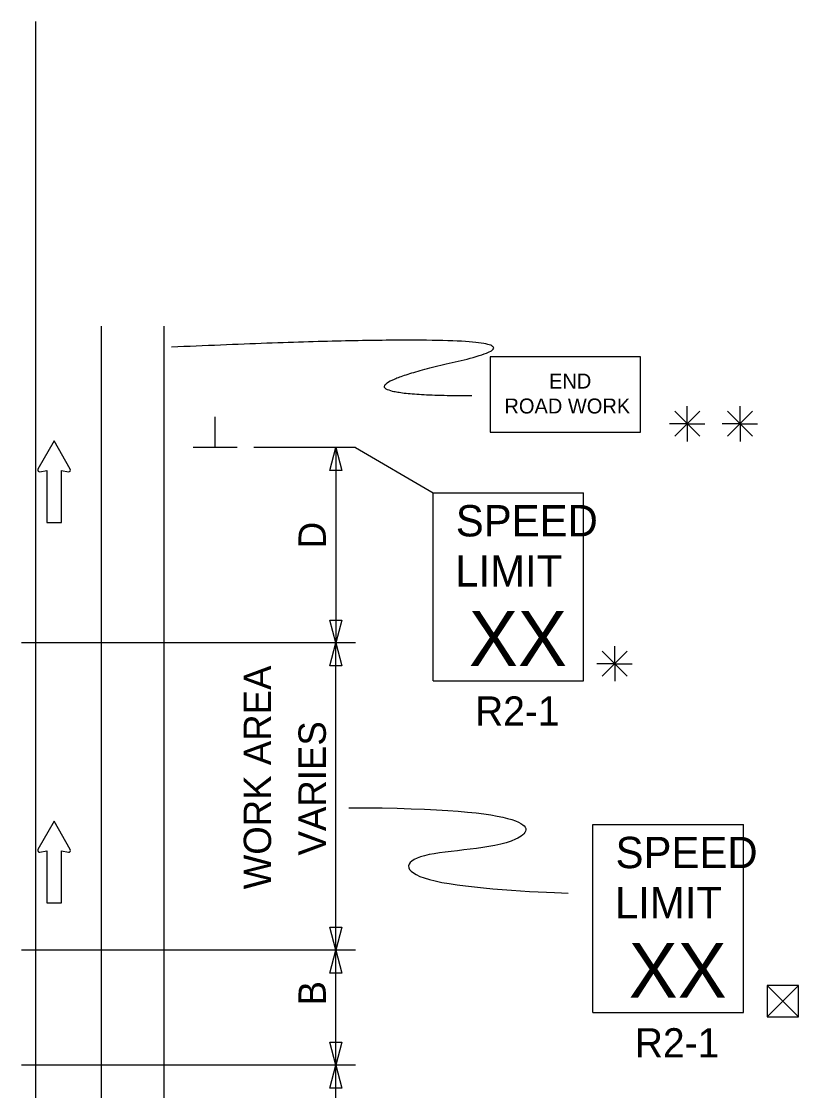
# Model space of a CAD drawing. Extents: x 16726 to 18479, y 5932 to 7023.
# Drawn here: x 16950.3 to 17149, y 6732.2 to 7005.6 of the extents above; entities that cross this region are included whole.
import ezdxf

# ---------------------------------------------------------------- set-up
doc = ezdxf.new("R2010")
doc.units = 0
for name, color, linetype in [('ALI_LEGAL_EX', 7, 'Continuous'), ('MT_SCRATCH_LEVEL_E', 7, 'Continuous'), ('PAVT_EDGE_EX', 7, 'Continuous'), ('TRAFFIC_SIGNS_PR', 7, 'Continuous'), ('TYPICAL_TEXT_DIMEN_PR', 7, 'Continuous')]:
    doc.layers.add(name, color=color, linetype=linetype)

msp = doc.modelspace()

# ---------------------------------------------------------------- linework, layer by layer
at = {"layer": 'ALI_LEGAL_EX'}
msp.add_line((16953.88, 7005.57), (16953.88, 6176.39), dxfattribs=at)
msp.add_line((16953.88, 7005.57), (16953.88, 6176.39), dxfattribs=at)
at = {"layer": 'MT_SCRATCH_LEVEL_E'}
for p, q in [((16958.65, 6898.33), (16954.54, 6891.09)), ((16962.8, 6891.09), (16958.65, 6898.33)), ((16955.02, 6890.41), (16956.8, 6890.72)), ((16956.8, 6890.72), (16956.8, 6877.46)), ((16960.54, 6877.46), (16960.54, 6890.72)), ((16960.54, 6890.72), (16962.32, 6890.41)), ((16956.8, 6877.46), (16960.54, 6877.46)), ((16958.65, 6801.06), (16954.54, 6793.82)), ((16962.8, 6793.82), (16958.65, 6801.06)), ((16955.02, 6793.13), (16956.8, 6793.45)), ((16956.8, 6793.45), (16956.8, 6780.19)), ((16960.54, 6780.19), (16960.54, 6793.45)), ((16960.54, 6793.45), (16962.32, 6793.13)), ((16956.8, 6780.19), (16960.54, 6780.19))]:
    msp.add_line(p, q, dxfattribs=at)
for centre, start, end in [((16954.95, 6890.87), 150.4248, 279.9638), ((16962.39, 6890.87), 260.0362, 29.7731), ((16954.95, 6793.59), 150.4248, 279.9638), ((16962.39, 6793.59), 260.0362, 29.7731)]:
    msp.add_arc(centre, 0.463, start, end, dxfattribs=at)
at = {"layer": 'PAVT_EDGE_EX'}
for p, q in [((16970.69, 6927.61), (16970.69, 6215.05)), ((16986.69, 6927.61), (16986.69, 6215.05))]:
    msp.add_line(p, q, dxfattribs=at)
at = {"layer": 'TRAFFIC_SIGNS_PR'}
for p, q in [((17055.59, 6885.03), (17094.03, 6885.03)), ((17055.59, 6836.97), (17055.59, 6885.03)), ((17094.03, 6836.97), (17094.03, 6885.03)), ((17055.59, 6836.97), (17094.03, 6836.97)), ((17096.43, 6800.2), (17134.88, 6800.2)), ((17096.43, 6752.14), (17096.43, 6800.2)), ((17134.88, 6752.14), (17134.88, 6800.2)), ((17096.43, 6752.14), (17134.88, 6752.14))]:
    msp.add_line(p, q, dxfattribs=at)
msp.add_lwpolyline([(17070.18, 6900.57), (17108.58, 6900.57), (17108.58, 6919.77), (17070.18, 6919.77)], close=True, dxfattribs=at)
msp.add_open_spline([(17065.47, 6909.8), (17022.96, 6909.8), (17099.47, 6927.21), (16988.69, 6922.27)], degree=2, dxfattribs=at)
at = {"layer": 'TYPICAL_TEXT_DIMEN_PR'}
for p, q in [((17120.52, 6902.69), (17120.52, 6907.15)), ((17134.03, 6902.69), (17134.03, 6907.15)), ((16999.82, 6896.64), (16999.82, 6904.42)), ((17117.33, 6905.88), (17123.71, 6899.5)), ((17123.71, 6905.88), (17117.33, 6899.5)), ((17130.84, 6905.88), (17137.21, 6899.5)), ((17137.21, 6905.88), (17130.84, 6899.5)), ((17120.52, 6902.69), (17115.99, 6902.69)), ((17120.52, 6902.69), (17123.71, 6902.69)), ((17120.52, 6902.69), (17125, 6902.69)), ((17120.52, 6902.69), (17120.52, 6898.19)), ((17134.03, 6902.69), (17129.49, 6902.69)), ((17134.03, 6902.69), (17137.21, 6902.69)), ((17134.03, 6902.69), (17138.5, 6902.69)), ((17134.03, 6902.69), (17134.03, 6898.19)), ((17005.44, 6896.64), (16994.19, 6896.64)), ((17035.69, 6896.64), (17009.69, 6896.64)), ((17029.12, 6890.77), (17030.69, 6896.64)), ((17030.69, 6896.64), (17030.69, 6846.64)), ((17030.69, 6896.64), (17032.26, 6890.77)), ((17035.69, 6896.64), (17055.59, 6885.03)), ((17030.69, 6890.77), (17029.12, 6890.77)), ((17032.26, 6890.77), (17030.69, 6890.77)), ((17030.69, 6846.64), (17029.12, 6852.5)), ((17029.12, 6852.5), (17030.69, 6852.5)), ((17030.69, 6852.5), (17032.26, 6852.5)), ((17032.26, 6852.5), (17030.69, 6846.64)), ((17035.69, 6846.64), (16950.31, 6846.64)), ((17029.12, 6840.77), (17030.69, 6846.64)), ((17030.69, 6768.1), (17030.69, 6846.64)), ((17030.69, 6846.64), (17032.26, 6840.77)), ((17098.79, 6844.52), (17105.16, 6838.14)), ((17105.16, 6844.52), (17098.79, 6838.14)), ((17101.97, 6841.33), (17101.97, 6845.79)), ((17030.69, 6840.77), (17029.12, 6840.77)), ((17032.26, 6840.77), (17030.69, 6840.77)), ((17101.97, 6841.33), (17097.44, 6841.33)), ((17101.97, 6841.33), (17105.16, 6841.33)), ((17101.97, 6841.33), (17106.45, 6841.33)), ((17101.97, 6841.33), (17101.97, 6836.83)), ((17030.69, 6768.1), (17029.12, 6773.96)), ((17029.12, 6773.96), (17030.69, 6773.96)), ((17030.69, 6773.96), (17032.26, 6773.96)), ((17032.26, 6773.96), (17030.69, 6768.1)), ((17035.69, 6768.1), (16950.31, 6768.1)), ((17029.12, 6762.24), (17030.69, 6768.1)), ((17030.69, 6738.67), (17030.69, 6768.1)), ((17030.69, 6768.1), (17032.26, 6762.24)), ((17030.69, 6762.24), (17029.12, 6762.24)), ((17032.26, 6762.24), (17030.69, 6762.24)), ((17140.99, 6759.03), (17148.99, 6751.03)), ((17140.99, 6751.03), (17148.99, 6759.03)), ((17030.69, 6738.67), (17029.12, 6744.53)), ((17029.12, 6744.53), (17030.69, 6744.53)), ((17030.69, 6744.53), (17032.26, 6744.53)), ((17032.26, 6744.53), (17030.69, 6738.67)), ((17035.69, 6738.67), (16950.31, 6738.67)), ((17029.12, 6732.81), (17030.69, 6738.67)), ((17030.69, 6708.11), (17030.69, 6738.67)), ((17030.69, 6738.67), (17032.26, 6732.81)), ((17030.69, 6732.81), (17029.12, 6732.81)), ((17032.26, 6732.81), (17030.69, 6732.81))]:
    msp.add_line(p, q, dxfattribs=at)
msp.add_lwpolyline([(17140.99, 6759.03), (17140.99, 6751.03), (17148.99, 6751.03), (17148.99, 6759.03)], close=True, dxfattribs=at)
msp.add_open_spline([(17034, 6804.5), (17082.47, 6804.5), (17082.47, 6793.75), (17047.55, 6793.75), (17047.55, 6784.7), (17081.76, 6782.94), (17090.05, 6782.65)], degree=3, dxfattribs=at)

# ---------------------------------------------------------------- texts
at = {"layer": 'TRAFFIC_SIGNS_PR'}
for s, height, p in [('END', 3.831, (17085.18, 6911.69)), ('ROAD WORK', 3.831, (17073.79, 6905.31)), ('SPEED', 8.01, (17061.36, 6873.88)), ('LIMIT', 8.01, (17061.2, 6861.06)), ('XX', 14.048, (17064.71, 6840.73)), ('R2-1', 7.449, (17066.28, 6825.52)), ('SPEED', 8.01, (17102.2, 6789.05)), ('LIMIT', 8.01, (17102.04, 6776.23)), ('XX', 14.048, (17105.55, 6755.9)), ('R2-1', 7.449, (17107.12, 6740.68))]:
    msp.add_text(s, height=height, dxfattribs=at).set_placement(p)
at = {"layer": 'TYPICAL_TEXT_DIMEN_PR'}
for s, p in [('D', (17028.14, 6870.85)), ('WORK AREA', (17014.14, 6783.65)), ('VARIES', (17028.14, 6792.29)), ('B', (17028.14, 6753.94))]:
    msp.add_text(s, height=7, rotation=90, dxfattribs=at).set_placement(p)

doc.saveas('drawing.dxf')
